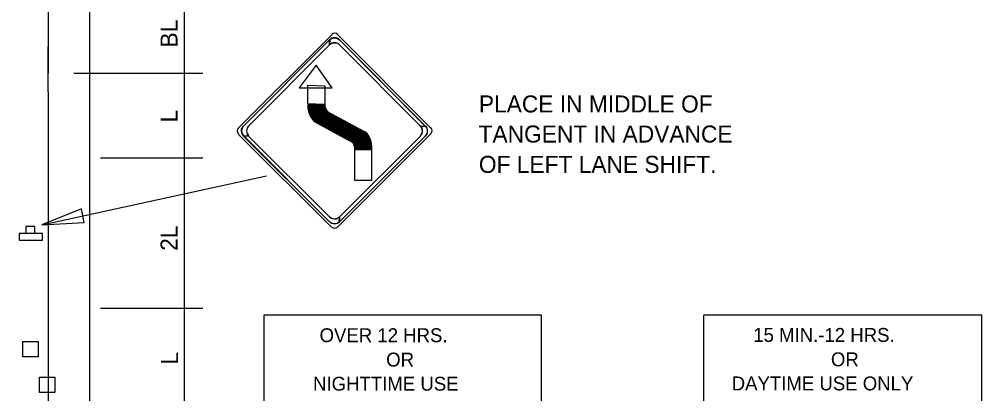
# Model space of a CAD drawing. Extents: x 15312.2 to 15319.5, y 15309 to 15319.2.
# Drawn here: x 15315.929 to 15319.325, y 15313.657 to 15314.978 of the extents above; entities that cross this region are included whole.
import ezdxf

# ---------------------------------------------------------------- set-up
doc = ezdxf.new("R2010")
doc.units = 0
for name, color, linetype in [('DETL-DIMS', 7, 'Continuous'), ('DETL-LINE', 7, 'Continuous'), ('DETL-NOTE', 7, 'Continuous'), ('USER-BORD', 7, 'Continuous')]:
    doc.layers.add(name, color=color, linetype=linetype)

# ---------------------------------------------------------------- blocks, each defined once
blk = doc.blocks.new('CD1')
at = {"layer": 'USER-BORD'}
blk.add_lwpolyline([(0, 0.031), (0.031, 0.031), (0.031, 0), (0, 0)], close=True, dxfattribs=at)
blk = doc.blocks.new('SIGN13')
at = {"layer": 'USER-BORD'}
for points in [[(-0.013, 0.018), (0.011, 0.019), (0.011, 0.037), (-0.013, 0.037)], [(-0.031, 0.018), (-0.031, 0), (0.032, 0), (0.032, 0.018)]]:
    blk.add_lwpolyline(points, close=True, dxfattribs=at)

msp = doc.modelspace()

# ---------------------------------------------------------------- linework, layer by layer
at = {"layer": 'DETL-DIMS'}
for p, q in [((15316.512, 15314.788), (15316.512, 15315.065)), ((15316.122, 15314.788), (15316.577, 15314.788)), ((15316.512, 15314.489), (15316.512, 15314.788)), ((15316.216, 15314.489), (15316.577, 15314.489)), ((15316.5124, 15313.9597), (15316.5124, 15314.4897)), ((15316.009, 15314.253), (15316.802, 15314.425)), ((15316.216, 15313.959), (15316.577, 15313.959)), ((15316.5124, 15313.6207), (15316.5124, 15313.9597))]:
    msp.add_line(p, q, dxfattribs=at)
msp.add_lwpolyline([(15316.159, 15314.261), (15316.149, 15314.309), (15316.009, 15314.253)], close=True, dxfattribs=at)
at = {"layer": 'DETL-LINE'}
for p, q in [((15316.031, 15318.785), (15316.031, 15314.788)), ((15316.177, 15318.785), (15316.177, 15310.694)), ((15317.032, 15314.923), (15316.702, 15314.594)), ((15316.721, 15314.601), (15317.024, 15314.905)), ((15317.382, 15314.594), (15317.053, 15314.923)), ((15317.059, 15314.905), (15317.362, 15314.601)), ((15316.031, 15314.722), (15316.031, 15314.881)), ((15317.024, 15314.887), (15316.738, 15314.601)), ((15317.345, 15314.601), (15317.059, 15314.887)), ((15316.031, 15314.722), (15316.031, 15310.694)), ((15316.948, 15314.66), (15316.967, 15314.678)), ((15316.948, 15314.661), (15316.966, 15314.678)), ((15316.948, 15314.662), (15316.964, 15314.678)), ((15316.948, 15314.664), (15316.962, 15314.678)), ((15316.948, 15314.665), (15316.961, 15314.678)), ((15316.948, 15314.666), (15316.96, 15314.678)), ((15316.948, 15314.668), (15316.958, 15314.678)), ((15316.948, 15314.669), (15316.957, 15314.678)), ((15316.948, 15314.67), (15316.955, 15314.678)), ((15316.948, 15314.672), (15316.954, 15314.678)), ((15316.948, 15314.674), (15316.953, 15314.678)), ((15316.948, 15314.675), (15316.951, 15314.678)), ((15316.948, 15314.677), (15316.949, 15314.678)), ((15316.948, 15314.678), (15317.007, 15314.677)), ((15316.949, 15314.655), (15316.972, 15314.678)), ((15316.949, 15314.656), (15316.972, 15314.678)), ((15316.949, 15314.657), (15316.97, 15314.678)), ((15316.949, 15314.658), (15316.968, 15314.678)), ((15316.95, 15314.651), (15316.977, 15314.678)), ((15316.95, 15314.652), (15316.976, 15314.678)), ((15316.95, 15314.654), (15316.974, 15314.678)), ((15316.951, 15314.649), (15316.98, 15314.678)), ((15316.951, 15314.65), (15316.978, 15314.678)), ((15316.952, 15314.647), (15316.983, 15314.678)), ((15316.952, 15314.648), (15316.981, 15314.678)), ((15316.953, 15314.642), (15316.99, 15314.678)), ((15316.953, 15314.642), (15316.989, 15314.678)), ((15316.953, 15314.643), (15316.987, 15314.678)), ((15316.953, 15314.645), (15316.986, 15314.678)), ((15316.953, 15314.646), (15316.984, 15314.678)), ((15316.954, 15314.641), (15316.991, 15314.678)), ((15316.955, 15314.638), (15316.995, 15314.678)), ((15316.955, 15314.639), (15316.993, 15314.678)), ((15316.956, 15314.637), (15316.997, 15314.678)), ((15316.956, 15314.637), (15316.995, 15314.678)), ((15316.957, 15314.634), (15317, 15314.678)), ((15316.957, 15314.636), (15316.999, 15314.678)), ((15316.958, 15314.632), (15317.005, 15314.678)), ((15316.958, 15314.633), (15317.003, 15314.678)), ((15316.958, 15314.633), (15317.001, 15314.678)), ((15316.959, 15314.631), (15317.006, 15314.678)), ((15316.96, 15314.63), (15317.007, 15314.678)), ((15316.96, 15314.629), (15317.007, 15314.676)), ((15316.961, 15314.628), (15317.008, 15314.675)), ((15316.962, 15314.628), (15317.008, 15314.673)), ((15316.962, 15314.627), (15317.008, 15314.672)), ((15316.962, 15314.626), (15317.008, 15314.67)), ((15316.963, 15314.625), (15317.008, 15314.67)), ((15316.964, 15314.624), (15317.009, 15314.668)), ((15316.965, 15314.623), (15317.009, 15314.667)), ((15316.965, 15314.623), (15317.009, 15314.666)), ((15316.966, 15314.622), (15317.009, 15314.665)), ((15316.967, 15314.621), (15317.009, 15314.664)), ((15316.967, 15314.62), (15317.01, 15314.663)), ((15316.968, 15314.619), (15317.01, 15314.661)), ((15316.969, 15314.619), (15317.011, 15314.661)), ((15316.97, 15314.618), (15317.011, 15314.66)), ((15316.97, 15314.617), (15317.012, 15314.659)), ((15316.971, 15314.616), (15317.013, 15314.658)), ((15316.972, 15314.615), (15317.014, 15314.656)), ((15316.972, 15314.616), (15317.013, 15314.656)), ((15316.974, 15314.614), (15317.014, 15314.655)), ((15316.975, 15314.614), (15317.014, 15314.654)), ((15316.976, 15314.614), (15317.015, 15314.653)), ((15316.976, 15314.613), (15317.016, 15314.652)), ((15316.977, 15314.613), (15317.017, 15314.652)), ((15316.978, 15314.612), (15317.018, 15314.651)), ((15316.979, 15314.612), (15317.019, 15314.651)), ((15316.981, 15314.611), (15317.019, 15314.651)), ((15316.981, 15314.61), (15317.02, 15314.65)), ((15316.982, 15314.61), (15317.022, 15314.649)), ((15316.983, 15314.609), (15317.023, 15314.649)), ((15316.984, 15314.609), (15317.023, 15314.648)), ((15316.985, 15314.609), (15317.024, 15314.648)), ((15316.986, 15314.608), (15317.025, 15314.647)), ((15316.987, 15314.608), (15317.026, 15314.647)), ((15316.988, 15314.607), (15317.028, 15314.647)), ((15316.989, 15314.606), (15317.028, 15314.646)), ((15316.99, 15314.606), (15317.029, 15314.646)), ((15316.991, 15314.605), (15317.03, 15314.645)), ((15316.991, 15314.605), (15317.031, 15314.644)), ((15316.993, 15314.604), (15317.032, 15314.644)), ((15316.994, 15314.604), (15317.033, 15314.643)), ((15316.995, 15314.603), (15317.035, 15314.642)), ((15316.995, 15314.604), (15317.034, 15314.642)), ((15316.996, 15314.602), (15317.036, 15314.642)), ((15316.997, 15314.602), (15317.037, 15314.642)), ((15316.998, 15314.601), (15317.038, 15314.641)), ((15317, 15314.6), (15317.04, 15314.64)), ((15317, 15314.601), (15317.038, 15314.64)), ((15317.001, 15314.6), (15317.041, 15314.639)), ((15317.002, 15314.6), (15317.042, 15314.639)), ((15317.003, 15314.599), (15317.042, 15314.638)), ((15317.004, 15314.599), (15317.043, 15314.637)), ((15317.005, 15314.598), (15317.044, 15314.637)), ((15317.006, 15314.597), (15317.045, 15314.637)), ((15317.007, 15314.597), (15317.047, 15314.636)), ((15317.008, 15314.596), (15317.047, 15314.636)), ((15317.009, 15314.595), (15317.049, 15314.635)), ((15317.009, 15314.595), (15317.048, 15314.635)), ((15317.01, 15314.595), (15317.05, 15314.634)), ((15317.012, 15314.595), (15317.051, 15314.633)), ((15317.013, 15314.594), (15317.052, 15314.633)), ((15317.014, 15314.593), (15317.054, 15314.633)), ((15317.014, 15314.593), (15317.053, 15314.633)), ((15317.015, 15314.592), (15317.055, 15314.632)), ((15317.016, 15314.652), (15317.149, 15314.581)), ((15317.016, 15314.592), (15317.056, 15314.631)), ((15317.017, 15314.591), (15317.056, 15314.631)), ((15317.019, 15314.59), (15317.057, 15314.63)), ((15317.019, 15314.59), (15317.059, 15314.629)), ((15317.02, 15314.59), (15317.06, 15314.629)), ((15316.972, 15314.616), (15317.104, 15314.544)), ((15317.021, 15314.589), (15317.061, 15314.628)), ((15317.022, 15314.589), (15317.061, 15314.628)), ((15317.023, 15314.588), (15317.062, 15314.628)), ((15317.023, 15314.588), (15317.063, 15314.627)), ((15317.025, 15314.587), (15317.064, 15314.627)), ((15317.026, 15314.586), (15317.066, 15314.626)), ((15317.027, 15314.586), (15317.066, 15314.626)), ((15317.028, 15314.586), (15317.067, 15314.625)), ((15317.028, 15314.585), (15317.068, 15314.624)), ((15317.029, 15314.585), (15317.069, 15314.624)), ((15317.031, 15314.584), (15317.07, 15314.623)), ((15317.032, 15314.584), (15317.071, 15314.623)), ((15317.033, 15314.583), (15317.072, 15314.623)), ((15317.033, 15314.582), (15317.073, 15314.622)), ((15317.034, 15314.582), (15317.074, 15314.622)), ((15317.035, 15314.581), (15317.075, 15314.621)), ((15317.036, 15314.581), (15317.075, 15314.62)), ((15317.038, 15314.581), (15317.076, 15314.62)), ((15317.038, 15314.58), (15317.078, 15314.619)), ((15317.039, 15314.58), (15317.079, 15314.619)), ((15317.04, 15314.579), (15317.08, 15314.619)), ((15317.041, 15314.578), (15317.08, 15314.618)), ((15317.042, 15314.578), (15317.081, 15314.618)), ((15317.042, 15314.577), (15317.082, 15314.617)), ((15317.044, 15314.577), (15317.084, 15314.616)), ((15317.045, 15314.576), (15317.085, 15314.616)), ((15317.046, 15314.576), (15317.085, 15314.615)), ((15317.047, 15314.576), (15317.086, 15314.615)), ((15317.047, 15314.575), (15317.087, 15314.614)), ((15317.048, 15314.574), (15317.088, 15314.614)), ((15317.05, 15314.574), (15317.089, 15314.614)), ((15317.051, 15314.573), (15317.09, 15314.613)), ((15317.052, 15314.573), (15317.091, 15314.613)), ((15317.052, 15314.572), (15317.092, 15314.612)), ((15317.053, 15314.572), (15317.093, 15314.611)), ((15317.054, 15314.572), (15317.094, 15314.611)), ((15317.055, 15314.571), (15317.094, 15314.61)), ((15317.056, 15314.571), (15317.096, 15314.609)), ((15317.057, 15314.57), (15317.097, 15314.609)), ((15317.058, 15314.569), (15317.098, 15314.609)), ((15317.059, 15314.569), (15317.099, 15314.609)), ((15317.06, 15314.568), (15317.099, 15314.608)), ((15317.061, 15314.567), (15317.1, 15314.607)), ((15317.061, 15314.567), (15317.101, 15314.607)), ((15317.063, 15314.567), (15317.103, 15314.606)), ((15317.064, 15314.567), (15317.103, 15314.606)), ((15317.065, 15314.566), (15317.104, 15314.605)), ((15317.066, 15314.565), (15317.105, 15314.604)), ((15317.066, 15314.565), (15317.106, 15314.604)), ((15317.067, 15314.564), (15317.107, 15314.604)), ((15317.069, 15314.563), (15317.108, 15314.603)), ((15317.07, 15314.563), (15317.109, 15314.603)), ((15317.07, 15314.562), (15317.11, 15314.602)), ((15317.071, 15314.562), (15317.111, 15314.602)), ((15317.072, 15314.562), (15317.112, 15314.601)), ((15317.073, 15314.561), (15317.113, 15314.6)), ((15317.074, 15314.561), (15317.113, 15314.6)), ((15317.075, 15314.56), (15317.115, 15314.6)), ((15317.076, 15314.56), (15317.116, 15314.6)), ((15317.077, 15314.559), (15317.117, 15314.599)), ((15317.078, 15314.558), (15317.117, 15314.598)), ((15317.079, 15314.558), (15317.118, 15314.598)), ((15317.08, 15314.557), (15317.119, 15314.597)), ((15317.08, 15314.557), (15317.121, 15314.596)), ((15317.082, 15314.557), (15317.122, 15314.596)), ((15317.083, 15314.556), (15317.122, 15314.595)), ((15317.084, 15314.556), (15317.123, 15314.595)), ((15317.085, 15314.555), (15317.124, 15314.595)), ((15316.702, 15314.573), (15317.031, 15314.244)), ((15317.024, 15314.263), (15316.721, 15314.566)), ((15316.738, 15314.566), (15317.024, 15314.281)), ((15317.052, 15314.244), (15317.382, 15314.574)), ((15317.362, 15314.566), (15317.059, 15314.263)), ((15317.059, 15314.281), (15317.345, 15314.566)), ((15317.085, 15314.554), (15317.125, 15314.594)), ((15317.086, 15314.554), (15317.126, 15314.594)), ((15317.087, 15314.553), (15317.127, 15314.593)), ((15317.089, 15314.553), (15317.128, 15314.593)), ((15317.089, 15314.553), (15317.129, 15314.592)), ((15317.09, 15314.552), (15317.13, 15314.591)), ((15317.091, 15314.552), (15317.131, 15314.591)), ((15317.092, 15314.551), (15317.131, 15314.59)), ((15317.093, 15314.55), (15317.132, 15314.59)), ((15317.094, 15314.55), (15317.134, 15314.59)), ((15317.095, 15314.549), (15317.135, 15314.589)), ((15317.096, 15314.549), (15317.136, 15314.589)), ((15317.097, 15314.548), (15317.136, 15314.588)), ((15317.098, 15314.548), (15317.137, 15314.587)), ((15317.099, 15314.548), (15317.138, 15314.587)), ((15317.099, 15314.547), (15317.14, 15314.586)), ((15317.101, 15314.546), (15317.141, 15314.586)), ((15317.102, 15314.546), (15317.141, 15314.586)), ((15317.103, 15314.545), (15317.142, 15314.585)), ((15317.103, 15314.545), (15317.143, 15314.585)), ((15317.104, 15314.544), (15317.144, 15314.584)), ((15317.105, 15314.543), (15317.145, 15314.584)), ((15317.106, 15314.543), (15317.146, 15314.583)), ((15317.107, 15314.542), (15317.147, 15314.582)), ((15317.107, 15314.541), (15317.148, 15314.582)), ((15317.108, 15314.54), (15317.149, 15314.581)), ((15317.108, 15314.539), (15317.15, 15314.581)), ((15317.108, 15314.539), (15317.15, 15314.58)), ((15317.109, 15314.538), (15317.151, 15314.58)), ((15317.11, 15314.537), (15317.152, 15314.579)), ((15317.11, 15314.535), (15317.153, 15314.578)), ((15317.111, 15314.534), (15317.153, 15314.577)), ((15317.111, 15314.534), (15317.154, 15314.576)), ((15317.112, 15314.533), (15317.155, 15314.576)), ((15317.112, 15314.531), (15317.155, 15314.575)), ((15317.113, 15314.53), (15317.156, 15314.574)), ((15317.113, 15314.529), (15317.156, 15314.573)), ((15317.113, 15314.528), (15317.157, 15314.572)), ((15317.113, 15314.527), (15317.158, 15314.572)), ((15317.113, 15314.525), (15317.159, 15314.571)), ((15317.113, 15314.524), (15317.159, 15314.57)), ((15317.113, 15314.523), (15317.16, 15314.569)), ((15317.113, 15314.521), (15317.16, 15314.568)), ((15317.113, 15314.52), (15317.161, 15314.567)), ((15317.114, 15314.519), (15317.161, 15314.567)), ((15317.116, 15314.519), (15317.162, 15314.566)), ((15317.117, 15314.519), (15317.163, 15314.564)), ((15317.118, 15314.519), (15317.163, 15314.563)), ((15317.12, 15314.519), (15317.164, 15314.562)), ((15317.122, 15314.519), (15317.164, 15314.562)), ((15317.122, 15314.519), (15317.164, 15314.561)), ((15317.124, 15314.519), (15317.165, 15314.56)), ((15317.126, 15314.519), (15317.165, 15314.558)), ((15317.127, 15314.519), (15317.166, 15314.557)), ((15317.128, 15314.519), (15317.166, 15314.557)), ((15317.13, 15314.519), (15317.167, 15314.556)), ((15317.131, 15314.519), (15317.167, 15314.555)), ((15317.133, 15314.519), (15317.168, 15314.553)), ((15317.135, 15314.519), (15317.168, 15314.553)), ((15317.136, 15314.519), (15317.169, 15314.552)), ((15317.137, 15314.519), (15317.169, 15314.55)), ((15317.139, 15314.519), (15317.169, 15314.549)), ((15317.141, 15314.519), (15317.169, 15314.548)), ((15317.141, 15314.519), (15317.17, 15314.547)), ((15317.143, 15314.519), (15317.17, 15314.546)), ((15317.145, 15314.519), (15317.17, 15314.544)), ((15317.146, 15314.519), (15317.171, 15314.543)), ((15317.148, 15314.519), (15317.171, 15314.543)), ((15317.149, 15314.519), (15317.171, 15314.541)), ((15317.15, 15314.519), (15317.171, 15314.54)), ((15317.152, 15314.519), (15317.172, 15314.539)), ((15317.154, 15314.519), (15317.172, 15314.538)), ((15317.155, 15314.519), (15317.172, 15314.536)), ((15317.156, 15314.519), (15317.172, 15314.534)), ((15317.158, 15314.519), (15317.173, 15314.534)), ((15317.16, 15314.519), (15317.173, 15314.532)), ((15317.161, 15314.519), (15317.173, 15314.531)), ((15317.162, 15314.519), (15317.173, 15314.529)), ((15317.164, 15314.519), (15317.173, 15314.528)), ((15317.113, 15314.519), (15317.172, 15314.519)), ((15317.165, 15314.519), (15317.173, 15314.526)), ((15317.167, 15314.519), (15317.173, 15314.525)), ((15317.168, 15314.519), (15317.173, 15314.524)), ((15317.169, 15314.519), (15317.173, 15314.522)), ((15317.171, 15314.519), (15317.173, 15314.52)), ((15316.7919, 15313.9348), (15316.7919, 15310.4706)), ((15317.772, 15313.9348), (15316.792, 15313.9348)), ((15317.7719, 15310.4706), (15317.7719, 15313.9348)), ((15318.3451, 15311.2117), (15318.3451, 15313.9348)), ((15319.3251, 15313.9348), (15318.3452, 15313.9348)), ((15319.3251, 15311.2117), (15319.3251, 15313.9348))]:
    msp.add_line(p, q, dxfattribs=at)
for points in [[(15316.721, 15314.601), (15317.015, 15314.896), (15317.025, 15314.906), (15317.024, 15314.887), (15316.738, 15314.601), (15316.734, 15314.595), (15316.731, 15314.586), (15316.732, 15314.578), (15316.734, 15314.572), (15316.738, 15314.566), (15316.721, 15314.566), (15316.716, 15314.574), (15316.714, 15314.583), (15316.714, 15314.59), (15316.717, 15314.596)], [(15317.059, 15314.905), (15317.353, 15314.61), (15317.363, 15314.6), (15317.345, 15314.601), (15317.059, 15314.887), (15317.053, 15314.892), (15317.044, 15314.894), (15317.035, 15314.894), (15317.03, 15314.891), (15317.024, 15314.887), (15317.024, 15314.905), (15317.031, 15314.91), (15317.041, 15314.912), (15317.048, 15314.911), (15317.053, 15314.909)], [(15316.977, 15314.816), (15316.917, 15314.736), (15317.034, 15314.736)], [(15316.948, 15314.745), (15317.007, 15314.743), (15317.007, 15314.677), (15316.948, 15314.68)], [(15317.362, 15314.566), (15317.068, 15314.272), (15317.058, 15314.262), (15317.059, 15314.281), (15317.345, 15314.566), (15317.349, 15314.573), (15317.352, 15314.582), (15317.351, 15314.59), (15317.349, 15314.596), (15317.345, 15314.601), (15317.362, 15314.601), (15317.367, 15314.594), (15317.369, 15314.585), (15317.369, 15314.578), (15317.367, 15314.572)], [(15317.024, 15314.263), (15316.73, 15314.558), (15316.72, 15314.568), (15316.738, 15314.566), (15317.024, 15314.281), (15317.03, 15314.276), (15317.039, 15314.274), (15317.048, 15314.274), (15317.054, 15314.277), (15317.059, 15314.281), (15317.059, 15314.263), (15317.052, 15314.258), (15317.042, 15314.256), (15317.036, 15314.257), (15317.03, 15314.259)], [(15317.113, 15314.409), (15317.113, 15314.524), (15317.172, 15314.524), (15317.172, 15314.409)]]:
    msp.add_lwpolyline(points, close=True, dxfattribs=at)
for centre, radius, start, end in [((15317.0421, 15314.8879), 0.0247, 45, 135), ((15317.0428, 15314.914), 0.0144, 45, 135), ((15317.042, 15314.8704), 0.0247, 45, 135), ((15317.0233, 15314.6709), 0.0751, 174.1008, 226.4986), ((15317.0434, 15314.6765), 0.0357, 177.4135, 221.9096), ((15316.7388, 15314.5846), 0.0247, 135, 225), ((15316.7563, 15314.5847), 0.0247, 135, 225), ((15317.3278, 15314.5846), 0.0247, 315, 45), ((15317.3453, 15314.5846), 0.0247, 315, 45), ((15317.3718, 15314.585), 0.0144, 315, 45), ((15316.713, 15314.5842), 0.0144, 135, 225), ((15317.0977, 15314.5274), 0.0751, 354.1008, 46.4986), ((15317.078, 15314.521), 0.0357, 357.4135, 41.9096), ((15317.042, 15314.2989), 0.0247, 225, 315), ((15317.0421, 15314.2814), 0.0247, 225, 315), ((15317.042, 15314.2552), 0.0144, 225, 315)]:
    msp.add_arc(centre, radius, start, end, dxfattribs=at)

# ---------------------------------------------------------------- block references
for name, p, xscale, yscale in [('SIGN13', (15315.97, 15314.199), 1.3077925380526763, 1.3077925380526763), ('CD1', (15315.942, 15313.787), 1.743723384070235, 1.743723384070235), ('CD1', (15316.001, 15313.662), 1.743723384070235, 1.743723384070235)]:
    msp.add_blockref(name, p, dxfattribs=dict(at, xscale=xscale, yscale=yscale))

# ---------------------------------------------------------------- texts
for s, height, p in [('OVER 12 HRS.', 0.049002, (15316.989, 15313.839)), ('15 MIN.-12 HRS.', 0.049002, (15318.519, 15313.84)), ('OR', 0.049, (15317.224, 15313.753)), ('OR', 0.049, (15318.793, 15313.754)), ('NIGHTTIME USE', 0.049002, (15316.966, 15313.668)), ('DAYTIME USE ONLY', 0.049002, (15318.443, 15313.669))]:
    msp.add_text(s, height=height, dxfattribs=at).set_placement(p)
at = {"layer": 'DETL-NOTE'}
for s, p in [('BL', (15316.488, 15314.878)), ('L', (15316.488, 15314.614)), ('2L', (15316.488, 15314.161)), ('L', (15316.49, 15313.76))]:
    msp.add_text(s, height=0.06, rotation=90, dxfattribs=at).set_placement(p)
for s, p in [('PLACE IN MIDDLE OF', (15317.551, 15314.649)), ('TANGENT IN ADVANCE', (15317.55, 15314.543)), ('OF LEFT LANE SHIFT.', (15317.551, 15314.436))]:
    msp.add_text(s, height=0.06, dxfattribs=at).set_placement(p)

doc.saveas('drawing.dxf')
